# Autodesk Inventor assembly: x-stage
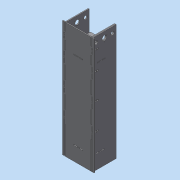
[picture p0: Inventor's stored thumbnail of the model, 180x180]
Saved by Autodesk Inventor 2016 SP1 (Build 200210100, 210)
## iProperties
Created: 2016-06
Part Number: x-stage
Document SubType Name: Assembly
Designer: Mohamed A.
Author: Mohamed A.
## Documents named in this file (6)
- C:\Users\Mohamed\Documents\inventor\machine_design\x-stage\x-stage.iam
- C:\Users\Mohamed\Documents\inventor\machine_design\stepper\body-box.ipt
- C:\Users\Mohamed\Documents\inventor\machine_design\x-stage\stepper-mount.ipt
- C:\Users\Mohamed\Documents\inventor\machine_design\x-stage\side.ipt
- C:\Users\Mohamed\Documents\inventor\machine_design\x-stage\side_outer.ipt
- C:\Users\Mohamed\Documents\inventor\machine_design\x-stage\back.ipt
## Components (6 placed, 5 different names)
1. body-box:1 — Mate:1, Mate:2, Mate:3, Mate:4
2. stepper-mount:1 — Mate:1, Mate:2, Mate:3, Mate:4, Mate:5, Mate:6, Mate:7, Mate:8
3. side:1 — Mate:5, Mate:6, Mate:7, Flush:1, Flush:2, Flush:3, Mate:9, Flush:4, Flush:7
4. side:2 — Flush:1, Flush:2, Mate:8, Flush:6
5. side_outer:1 — Flush:3, Mate:9, Flush:4, Mate:10
6. back:1 — Flush:6, Flush:7, Mate:10
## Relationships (16: Mate 10, Flush 6)
- Mate:1: body-box:1 ↔ stepper-mount:1
- Mate:2: body-box:1 ↔ stepper-mount:1
- Mate:3: body-box:1 ↔ stepper-mount:1
- Mate:4: body-box:1 ↔ stepper-mount:1
- Mate:5: stepper-mount:1 ↔ side:1
- Mate:6: stepper-mount:1 ↔ side:1
- Mate:7: stepper-mount:1 ↔ side:1
- Flush:1: side:1 ↔ side:2
- Flush:2: side:1 ↔ side:2
- Mate:8: stepper-mount:1 ↔ side:2
- Flush:3: side:1 ↔ side_outer:1
- Mate:9: side:1 ↔ side_outer:1
- Flush:4: side:1 ↔ side_outer:1
- Flush:6: side:2 ↔ back:1
- Flush:7: side:1 ↔ back:1
- Mate:10: side_outer:1 ↔ back:1
